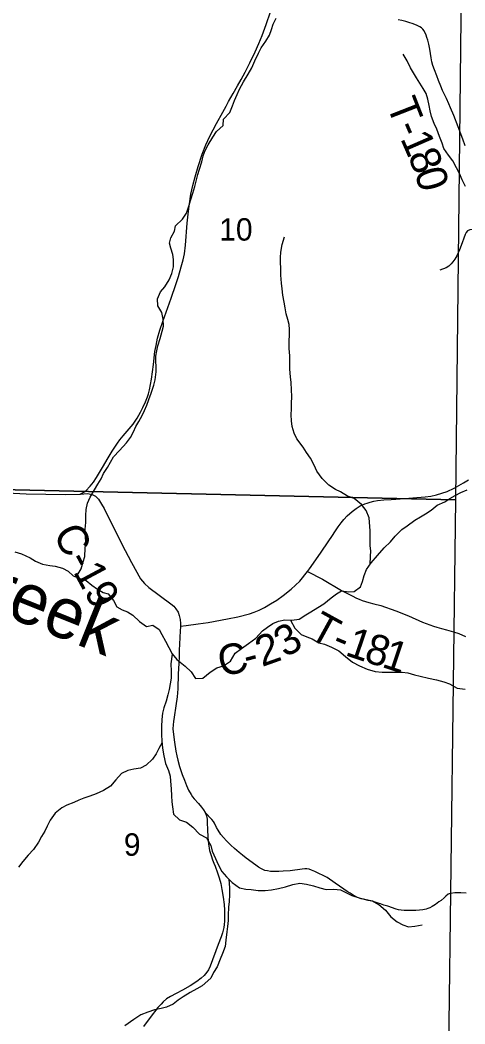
# Model space of a CAD drawing. Extents: x 0 to 34, y -8.9 to 22.
# Drawn here: x 26.904 to 27.734, y 8.236 to 10.111 of the extents above; entities that cross this region are included whole.
import ezdxf

# ---------------------------------------------------------------- set-up
doc = ezdxf.new("R2010")
doc.units = 0
for name, color, linetype in [('GM_X_Corporation', 7, 'Continuous'), ('GM_X_County_Road', 7, 'Continuous'), ('GM_X_County_Road_Text', 7, 'Continuous'), ('GM_X_Minor_River', 7, 'Continuous'), ('GM_X_Minor_River_Text', 7, 'Continuous'), ('GM_X_Section_Text', 7, 'Continuous'), ('GM_X_State_Route', 7, 'Continuous'), ('GM_X_Township_Road', 7, 'Continuous'), ('GM_X_Township_Road_Text', 7, 'Continuous')]:
    doc.layers.add(name, color=color, linetype=linetype)

msp = doc.modelspace()

# ---------------------------------------------------------------- linework, layer by layer
at = {"layer": 'GM_X_Corporation'}
for points in [[(26.7158, 10.2453), (27.7275, 10.2275), (27.7161, 9.2151), (26.7025, 9.2378)], [(27.7161, 9.2151), (27.7031, 8.1879), (26.6846, 8.2041), (26.7025, 9.2378)]]:
    msp.add_lwpolyline(points, close=True, dxfattribs=at)
at = {"layer": 'GM_X_County_Road'}
for points in [[(27.2035, 8.9792), (27.2141, 8.9805), (27.2362, 8.9832), (27.255, 8.9861), (27.2907, 8.9925), (27.3104, 8.9964), (27.3319, 9.0018), (27.3407, 9.0051), (27.35, 9.009), (27.3599, 9.014), (27.3714, 9.0205), (27.3829, 9.0279), (27.3946, 9.0363), (27.4098, 9.0484), (27.418, 9.0554), (27.4259, 9.0631), (27.4403, 9.0809), (27.4441, 9.0863), (27.4643, 9.1152), (27.4803, 9.1385), (27.4857, 9.1468), (27.4927, 9.1572), (27.4976, 9.1648), (27.5031, 9.1723), (27.5079, 9.1782), (27.5145, 9.1853), (27.5234, 9.193), (27.5309, 9.199), (27.5382, 9.2036), (27.5469, 9.2076), (27.5517, 9.2091), (27.5572, 9.2107), (27.5639, 9.2123), (27.571, 9.2136), (27.5826, 9.2148), (27.5962, 9.2158), (27.6218, 9.2176), (27.6369, 9.2188), (27.6596, 9.2207), (27.6703, 9.2221), (27.6809, 9.2243), (27.6908, 9.2272), (27.701, 9.2308), (27.7137, 9.2368), (27.7313, 9.2469), (27.7409, 9.2524)], [(27.0158, 9.2256), (27.0299, 9.2269), (27.0383, 9.2253), (27.0449, 9.2219), (27.0505, 9.2162), (27.0558, 9.2071), (27.0606, 9.1988), (27.0937, 9.1325), (27.1117, 9.0979), (27.1289, 9.0672), (27.1323, 9.0628), (27.1361, 9.0585), (27.1444, 9.051), (27.1854, 9.0209), (27.1905, 9.0162), (27.1947, 9.0117), (27.1987, 9.005), (27.2007, 8.9992), (27.2025, 8.9917), (27.2034, 8.9842), (27.2035, 8.9792), (27.2022, 8.9588), (27.2013, 8.9442), (27.201, 8.9354), (27.2005, 8.9232), (27.1999, 8.9093), (27.1989, 8.8897), (27.198, 8.8617), (27.1969, 8.8473), (27.1948, 8.8299), (27.1914, 8.8088), (27.1901, 8.801), (27.1896, 8.7946), (27.1892, 8.7872), (27.1894, 8.7815), (27.1918, 8.7621), (27.1946, 8.7456), (27.1961, 8.7371), (27.198, 8.7285), (27.2015, 8.7166), (27.2062, 8.7018), (27.2104, 8.6911), (27.2144, 8.6812), (27.2184, 8.6725), (27.2229, 8.6643), (27.2259, 8.6602), (27.2288, 8.6565), (27.2369, 8.6476), (27.2424, 8.6411), (27.2464, 8.6361), (27.2494, 8.6311), (27.2516, 8.6245), (27.2527, 8.6184), (27.2532, 8.6108), (27.2535, 8.6), (27.254, 8.5844), (27.2553, 8.5726), (27.2575, 8.5602), (27.2603, 8.5506), (27.2629, 8.5426), (27.2652, 8.5366), (27.2677, 8.531), (27.2723, 8.5183), (27.2754, 8.5088), (27.2782, 8.4984), (27.2805, 8.4874), (27.2826, 8.4727), (27.2846, 8.4593), (27.2851, 8.4488), (27.2852, 8.4282), (27.2846, 8.4216), (27.2838, 8.4162), (27.2815, 8.4064), (27.2789, 8.3986), (27.2736, 8.3846), (27.2587, 8.3438), (27.2556, 8.3371), (27.2525, 8.3324), (27.2473, 8.3265), (27.2416, 8.3212), (27.2337, 8.315), (27.2212, 8.307), (27.2068, 8.2988), (27.1954, 8.293), (27.1847, 8.2872), (27.1772, 8.2828), (27.1709, 8.2774), (27.1669, 8.2732), (27.1612, 8.2666), (27.1466, 8.2479), (27.1339, 8.2311)]]:
    msp.add_lwpolyline(points, dxfattribs=at)
at = {"layer": 'GM_X_Minor_River'}
for points in [[(27.0088, 9.0707), (27.0181, 9.0861), (27.0219, 9.0994), (27.0249, 9.1093), (27.0256, 9.1249), (27.0264, 9.1359), (27.026, 9.1461), (27.0256, 9.1602), (27.0267, 9.1727), (27.0266, 9.186), (27.027, 9.197), (27.0296, 9.2088), (27.0345, 9.2198), (27.0425, 9.2335), (27.0489, 9.2441), (27.055, 9.2544), (27.0595, 9.2643), (27.067, 9.2753), (27.0723, 9.2856), (27.078, 9.2951), (27.0894, 9.3073), (27.1022, 9.3214), (27.1098, 9.3316), (27.1155, 9.3423), (27.12, 9.3518), (27.1253, 9.3613), (27.1317, 9.3727), (27.1362, 9.3822), (27.1404, 9.3921), (27.1442, 9.4024), (27.1483, 9.4145), (27.1532, 9.429), (27.1559, 9.4389), (27.1577, 9.454), (27.1581, 9.4635), (27.1569, 9.4738), (27.1573, 9.4837), (27.1588, 9.4935), (27.161, 9.503), (27.1652, 9.5167), (27.1689, 9.53), (27.1712, 9.5395), (27.1711, 9.5528), (27.1681, 9.5649), (27.1608, 9.5774), (27.1601, 9.5907), (27.1657, 9.6033), (27.174, 9.6132), (27.182, 9.6257), (27.1869, 9.6379), (27.1899, 9.6504), (27.1902, 9.6637), (27.1891, 9.6732), (27.1849, 9.6854), (27.183, 9.6948), (27.1852, 9.7047), (27.192, 9.7169), (27.1939, 9.7268), (27.2068, 9.7393), (27.2147, 9.7508), (27.2188, 9.7637), (27.2226, 9.7762), (27.2264, 9.788), (27.2301, 9.8002), (27.2332, 9.8131), (27.2354, 9.8226), (27.2384, 9.8329), (27.2433, 9.8465), (27.2456, 9.8579), (27.249, 9.8674), (27.255, 9.8781), (27.2637, 9.8926), (27.2705, 9.9028), (27.283, 9.9143), (27.2837, 9.9264), (27.2955, 9.9386), (27.3004, 9.9512), (27.3038, 9.9607), (27.309, 9.9724), (27.3136, 9.9823), (27.3208, 9.996), (27.3298, 10.0105), (27.3362, 10.0219), (27.3419, 10.0352), (27.3487, 10.0497), (27.3536, 10.0592), (27.3623, 10.0721), (27.3691, 10.0832), (27.3729, 10.0934), (27.3763, 10.1033), (27.3816, 10.1147)], [(27.7352, 9.8006), (27.7291, 9.8128), (27.7238, 9.8249), (27.7184, 9.8355), (27.7112, 9.8484), (27.7036, 9.8586), (27.6944, 9.8711), (27.6914, 9.881), (27.6868, 9.8935), (27.6818, 9.9072), (27.6765, 9.9178), (27.6715, 9.9311), (27.6692, 9.9417), (27.6673, 9.9516), (27.6646, 9.9633), (27.6619, 9.9739), (27.6562, 9.9834), (27.6497, 9.9937), (27.6437, 10.0031), (27.6383, 10.0126), (27.6326, 10.0221), (27.6261, 10.0354), (27.6185, 10.0475)], [(27.5571, 9.0945), (27.5577, 9.1095), (27.5584, 9.119), (27.5573, 9.13), (27.5572, 9.1569), (27.5556, 9.1812), (27.5495, 9.1952), (27.5408, 9.2066), (27.5275, 9.2176), (27.5149, 9.2217), (27.502, 9.23), (27.4925, 9.2345), (27.4803, 9.2425), (27.4678, 9.2546), (27.4575, 9.2686), (27.4526, 9.28), (27.4457, 9.2928), (27.4385, 9.3035), (27.4324, 9.3137), (27.4206, 9.3292), (27.4152, 9.3398), (27.4114, 9.3523), (27.4103, 9.3626), (27.4099, 9.3736), (27.4102, 9.385), (27.4102, 9.3949), (27.4109, 9.4081), (27.4105, 9.4207), (27.4097, 9.434), (27.4082, 9.4446), (27.407, 9.459), (27.4074, 9.4723), (27.407, 9.4841), (27.4062, 9.4977), (27.4061, 9.5114), (27.4065, 9.5235), (27.4065, 9.533), (27.4061, 9.5425), (27.4038, 9.552), (27.4007, 9.5626), (27.3988, 9.5736), (27.3969, 9.5843), (27.3945, 9.5975), (27.393, 9.6089), (27.3915, 9.6199), (27.3907, 9.6347), (27.3906, 9.648), (27.3899, 9.6583), (27.3898, 9.6678), (27.3906, 9.6776), (27.3932, 9.6921), (27.3973, 9.7061)], [(27.6035, 9.1472), (27.616, 9.1594), (27.6262, 9.1666), (27.6402, 9.1773), (27.6512, 9.1834), (27.6607, 9.1888), (27.6709, 9.196), (27.6823, 9.2048), (27.6963, 9.2116), (27.7058, 9.2174), (27.7157, 9.2231), (27.7263, 9.2288), (27.738, 9.2334)], [(26.8944, 9.118), (26.9065, 9.1139), (26.9229, 9.1067), (26.9327, 9.1007), (26.946, 9.0946), (26.9597, 9.0924), (26.9696, 9.0913), (26.9832, 9.0875), (26.9935, 9.0819), (27.003, 9.0728), (27.0155, 9.0683), (27.0273, 9.0645), (27.0376, 9.0558), (27.0486, 9.0479), (27.0588, 9.0418), (27.0683, 9.0392), (27.0782, 9.0271), (27.0843, 9.015), (27.0942, 9.0093), (27.1045, 9.0059), (27.1143, 8.9995), (27.1269, 8.9878), (27.1398, 8.9783), (27.1519, 8.981), (27.1633, 8.9727), (27.1683, 8.9632), (27.1755, 8.9507), (27.1813, 8.939), (27.1874, 8.9272), (27.1965, 8.9166), (27.2117, 8.9045), (27.2231, 8.8935), (27.2311, 8.8814), (27.2448, 8.8818), (27.2588, 8.8933), (27.2713, 8.9013), (27.2834, 8.9051), (27.2963, 8.9135), (27.305, 8.9283), (27.3171, 8.9375), (27.33, 8.9467), (27.344, 8.9569), (27.3561, 8.9703), (27.3656, 8.9771), (27.3758, 8.984), (27.3861, 8.9886), (27.3978, 8.9909), (27.4111, 8.9902), (27.4247, 8.9921), (27.4373, 9.0001), (27.4467, 9.0059), (27.4592, 9.0142), (27.4706, 9.0207), (27.4846, 9.0318), (27.4945, 9.0394), (27.5039, 9.0451), (27.5176, 9.0433), (27.5271, 9.0437), (27.5392, 9.0525), (27.543, 9.0623), (27.546, 9.0734), (27.5501, 9.0851), (27.5592, 9.0973), (27.571, 9.111), (27.5831, 9.1251), (27.5952, 9.1365), (27.6035, 9.1472)], [(27.4082, 8.9903), (27.4168, 8.9754), (27.4282, 8.9633), (27.4389, 8.9591), (27.4487, 8.9554), (27.4613, 8.9482), (27.4719, 8.9452), (27.4848, 8.9396), (27.4985, 8.9331), (27.511, 8.9226), (27.524, 8.912), (27.5373, 8.9048), (27.5517, 8.8984), (27.5665, 8.8943), (27.5794, 8.8928), (27.5908, 8.8928), (27.6041, 8.8932), (27.617, 8.8933), (27.6272, 8.8918), (27.6401, 8.8884), (27.6504, 8.8854), (27.6659, 8.8817), (27.6811, 8.8787), (27.6948, 8.8753), (27.7054, 8.8712), (27.7195, 8.8632), (27.7343, 8.8614)], [(27.1878, 8.9267), (27.1851, 8.9086), (27.1859, 8.8949), (27.1859, 8.8817), (27.1841, 8.8714), (27.1818, 8.8608), (27.1796, 8.8509), (27.1762, 8.8387), (27.172, 8.8266), (27.1698, 8.8167), (27.1687, 8.8049), (27.1675, 8.7913), (27.1676, 8.7765), (27.1687, 8.7639), (27.1699, 8.751), (27.1722, 8.7366), (27.1753, 8.7222), (27.181, 8.7093), (27.1837, 8.6991), (27.1848, 8.6896), (27.1856, 8.6752), (27.1864, 8.6619), (27.1872, 8.6509), (27.188, 8.6414), (27.1903, 8.6281), (27.2013, 8.6171), (27.2142, 8.6126), (27.2264, 8.6035), (27.2386, 8.5903), (27.2515, 8.5835), (27.2599, 8.5691), (27.2622, 8.5589), (27.2683, 8.5452), (27.2736, 8.5335), (27.2805, 8.5206), (27.2892, 8.5107), (27.2999, 8.5002), (27.3135, 8.4903), (27.3249, 8.4877), (27.3352, 8.487), (27.3481, 8.4855), (27.3614, 8.4852), (27.3731, 8.4867), (27.3864, 8.4887), (27.3993, 8.4921), (27.4129, 8.4963), (27.4262, 8.4987), (27.4384, 8.4968), (27.4513, 8.4942), (27.463, 8.49), (27.4752, 8.487), (27.4892, 8.4878), (27.5021, 8.4864), (27.5128, 8.4807), (27.523, 8.4758), (27.5367, 8.4717), (27.55, 8.4683), (27.5618, 8.4661), (27.5735, 8.4593), (27.5857, 8.4487), (27.596, 8.4358), (27.6078, 8.4267), (27.6184, 8.4211), (27.6286, 8.4173), (27.6408, 8.4185), (27.6544, 8.4208)], [(27.1689, 8.7618), (27.1631, 8.7506), (27.1578, 8.7407), (27.151, 8.7308), (27.1389, 8.7194), (27.1286, 8.7137), (27.1161, 8.7118), (27.1051, 8.7091), (27.0934, 8.7041), (27.0828, 8.6919), (27.0729, 8.6801), (27.0593, 8.6721), (27.0456, 8.6656), (27.0343, 8.6614), (27.0229, 8.6576), (27.0134, 8.6541), (27.0039, 8.6495), (26.9914, 8.6446), (26.9816, 8.6396), (26.9691, 8.6297), (26.96, 8.6164), (26.9547, 8.6053), (26.9498, 8.5958), (26.9441, 8.5859), (26.9381, 8.5753), (26.929, 8.5616), (26.9192, 8.5513), (26.9089, 8.5395), (26.901, 8.5289)], [(27.2936, 8.5064), (27.2946, 8.4903), (27.2946, 8.477), (27.2939, 8.4645), (27.2931, 8.4538), (27.2924, 8.439), (27.292, 8.4295), (27.2909, 8.4178), (27.2898, 8.4083), (27.2879, 8.3927), (27.2865, 8.3809), (27.2819, 8.3676), (27.277, 8.357), (27.2714, 8.3425), (27.2649, 8.3319), (27.2596, 8.3216), (27.2434, 8.3071), (27.2335, 8.3014), (27.221, 8.2949), (27.2085, 8.2865), (27.199, 8.2804), (27.1896, 8.2732), (27.1774, 8.2675), (27.1672, 8.2651), (27.155, 8.2625), (27.1422, 8.2579), (27.1293, 8.2529), (27.1164, 8.2441), (27.0993, 8.2323)]]:
    msp.add_lwpolyline(points, dxfattribs=at)
at = {"layer": 'GM_X_State_Route'}
msp.add_lwpolyline([(26.88, 9.2279), (26.9155, 9.2263), (26.952, 9.2259), (26.9891, 9.225), (27.0158, 9.2256), (27.0265, 9.232), (27.0348, 9.2404), (27.0407, 9.2482), (27.0464, 9.2568), (27.0579, 9.2757), (27.0681, 9.2933), (27.0757, 9.3061), (27.0804, 9.3136), (27.0855, 9.3208), (27.0902, 9.3272), (27.0964, 9.3348), (27.1148, 9.3564), (27.1225, 9.3677), (27.1289, 9.3791), (27.1332, 9.3873), (27.1377, 9.398), (27.1418, 9.4074), (27.1436, 9.4132), (27.1451, 9.4203), (27.149, 9.4403), (27.1528, 9.4681), (27.1556, 9.4921), (27.1578, 9.5035), (27.1604, 9.5172), (27.1649, 9.5321), (27.17, 9.548), (27.1857, 9.5918), (27.1946, 9.6174), (27.1997, 9.6322), (27.2046, 9.6501), (27.208, 9.6633), (27.2104, 9.6747), (27.2126, 9.691), (27.2158, 9.7319), (27.2177, 9.7487), (27.2192, 9.7635), (27.2228, 9.7862), (27.2264, 9.8022), (27.2304, 9.8185), (27.2359, 9.838), (27.2439, 9.8609), (27.2505, 9.878), (27.2582, 9.8943), (27.2702, 9.918), (27.2821, 9.9392), (27.2882, 9.9502), (27.293, 9.9592), (27.3015, 9.9743), (27.3094, 9.9887), (27.3163, 10.0005), (27.3238, 10.0139), (27.3328, 10.0316), (27.3425, 10.0522), (27.3495, 10.0673), (27.3555, 10.0823), (27.3634, 10.1028), (27.3712, 10.1266)], dxfattribs=at)
at = {"layer": 'GM_X_Township_Road'}
for points in [[(27.7345, 9.8766), (27.7298, 9.8888), (27.7214, 9.912), (27.7134, 9.9328), (27.7071, 9.9475), (27.7039, 9.955), (27.6993, 9.9645), (27.6923, 9.9795), (27.6888, 9.9877), (27.6845, 9.9983), (27.6814, 10.0068), (27.677, 10.018), (27.674, 10.0266), (27.6721, 10.0335), (27.6707, 10.041), (27.6683, 10.0567), (27.6664, 10.0664), (27.6645, 10.0738), (27.663, 10.0788), (27.6614, 10.0829), (27.6578, 10.0909), (27.6552, 10.094), (27.6527, 10.0965), (27.6497, 10.0985), (27.6448, 10.101), (27.6403, 10.1027), (27.6357, 10.1046), (27.6314, 10.1061), (27.624, 10.1086), (27.616, 10.1105), (27.6092, 10.1116)], [(27.7821, 9.7182), (27.7752, 9.7189), (27.77, 9.7191), (27.7557, 9.7197), (27.7481, 9.7199), (27.7429, 9.7191), (27.7387, 9.7175), (27.7363, 9.7146), (27.7343, 9.7105), (27.732, 9.704), (27.7286, 9.6953), (27.7236, 9.682), (27.7188, 9.6709), (27.7151, 9.6645), (27.7117, 9.6594), (27.7081, 9.6557), (27.7038, 9.6518), (27.6988, 9.6487), (27.6871, 9.6439)], [(27.4403, 9.0809), (27.4679, 9.0667), (27.5039, 9.0459), (27.5236, 9.0357), (27.5317, 9.0314), (27.5367, 9.0292), (27.542, 9.0271), (27.5545, 9.0235), (27.5643, 9.021), (27.5771, 9.0178), (27.6049, 9.0079), (27.6284, 8.9984), (27.6551, 8.9865), (27.6752, 8.9789), (27.6816, 8.9769), (27.6903, 8.9744), (27.6995, 8.9721), (27.7127, 8.9685), (27.7225, 8.9651), (27.7353, 8.96)], [(27.7045, 8.4788), (27.7029, 8.4782), (27.6986, 8.4748), (27.6953, 8.4715), (27.6899, 8.4668), (27.6855, 8.4638), (27.6793, 8.4593), (27.673, 8.4555), (27.6684, 8.4528), (27.6648, 8.4513), (27.6617, 8.4503), (27.6557, 8.4489), (27.649, 8.4483), (27.6422, 8.4478), (27.6304, 8.4476), (27.6207, 8.4477), (27.6152, 8.4482), (27.6101, 8.449), (27.6054, 8.4505), (27.5902, 8.4558), (27.5824, 8.4581), (27.5764, 8.4602), (27.572, 8.4618), (27.5685, 8.463), (27.561, 8.4652), (27.5532, 8.4666), (27.5463, 8.4682), (27.5401, 8.4699), (27.5338, 8.4723), (27.5253, 8.4768), (27.5197, 8.4802), (27.5142, 8.4835), (27.5082, 8.4877), (27.4917, 8.4989), (27.4771, 8.5095), (27.4537, 8.5209), (27.4479, 8.5234), (27.4435, 8.5249), (27.4392, 8.5255), (27.4354, 8.5256), (27.4301, 8.5252), (27.4077, 8.5221), (27.395, 8.5212), (27.3866, 8.5209), (27.3779, 8.5207), (27.3713, 8.521), (27.3656, 8.5217), (27.3606, 8.5229), (27.3546, 8.5254), (27.3487, 8.5291), (27.3435, 8.5323), (27.326, 8.5459), (27.3192, 8.551), (27.3125, 8.5562), (27.3043, 8.5634), (27.2972, 8.5699), (27.2889, 8.578), (27.2832, 8.5841), (27.2786, 8.5901), (27.2736, 8.5978), (27.2707, 8.6028), (27.2665, 8.6108), (27.2647, 8.6143), (27.2616, 8.6179), (27.2494, 8.6311)], [(27.7364, 8.4804), (27.7266, 8.481), (27.7152, 8.4811), (27.7069, 8.4798), (27.7045, 8.4788)]]:
    msp.add_lwpolyline(points, dxfattribs=at)

# ---------------------------------------------------------------- texts
at = {"layer": 'GM_X_County_Road_Text'}
for s, height, rotation, p in [('C-19', 0.05682, 298.2545, (26.9643, 9.1517)), ('3', 0.0568, 30.5897, (27.399, 8.9192)), ('2', 0.0568, 19.5484, (27.3552, 8.9025)), ('C', 0.0568, 12.4183, (27.2797, 8.8843)), ('-', 0.0568, 14.9304, (27.3279, 8.895))]:
    msp.add_text(s, height=height, rotation=rotation, dxfattribs=at).set_placement(p)
at = {"layer": 'GM_X_Minor_River_Text'}
msp.add_text('Creek', height=0.0947, rotation=338.1293, dxfattribs=at).set_placement((26.751, 9.0483))
at = {"layer": 'GM_X_Section_Text'}
for s, height, p in [('10', 0.04186, (27.2755, 9.6993)), ('9', 0.0419, (27.0975, 8.5502))]:
    msp.add_text(s, height=height, rotation=0, dxfattribs=at).set_placement(p)
at = {"layer": 'GM_X_Township_Road_Text'}
for s, rotation, p in [('T', 291.3581, (27.5871, 9.9534)), ('1', 293.5899, (27.6128, 9.8902)), ('-', 293.4444, (27.6035, 9.9117)), ('8', 292.3397, (27.6267, 9.8584)), ('0', 286.2985, (27.6395, 9.8275)), ('T', 331.2438, (27.4398, 8.9592)), ('1', 341.1997, (27.5084, 8.9254)), ('8', 343.199, (27.5436, 8.9134)), ('-', 337.1172, (27.4827, 8.936)), ('1', 341.7329, (27.5767, 8.9034))]:
    msp.add_text(s, height=0.0568, rotation=rotation, dxfattribs=at).set_placement(p)

doc.saveas('drawing.dxf')
